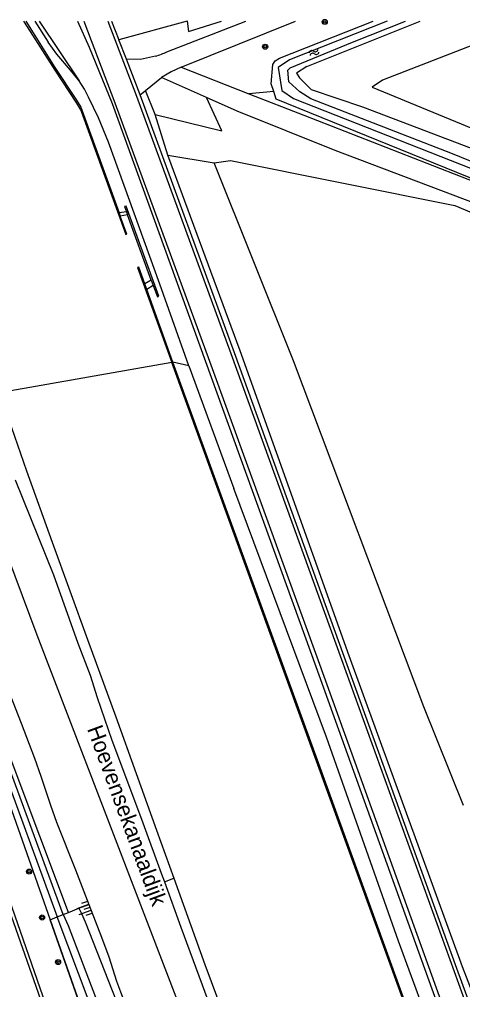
# Model space of a CAD drawing. Extents: x 135990 to 139000, y 393500 to 396000.
# Drawn here: x 136106.6 to 136176.4, y 395847.7 to 396000.3 of the extents above; entities that cross this region are included whole.
import ezdxf

# ---------------------------------------------------------------- set-up
doc = ezdxf.new("R2010")
doc.units = 0
for name, color, linetype in [('gg-afsc-hekwerk', 7, 'Continuous'), ('gg-anno-openbare ruimte label', 7, 'Continuous'), ('gg-knt-BGT kruinlijn', 7, 'Continuous'), ('gg-knt-bovenkant onderkant talud', 7, 'Continuous'), ('gg-knt-onverhard', 7, 'Continuous'), ('gg-knt-verharding', 7, 'Continuous'), ('gg-knt-verharding nz', 7, 'Continuous'), ('gg-kntw-bovenkant insteek waterloop', 7, 'Continuous'), ('gg-kntw-midden sloot', 7, 'Continuous'), ('gg-kntw-waterlijn', 7, 'Continuous'), ('gt-grn-groengrens', 7, 'Continuous'), ('gt-grn-vlakafsluiter', 7, 'Continuous'), ('gt-symb-boom', 7, 'Continuous'), ('gt-symb-talud symbool', 7, 'Continuous'), ('gt-symb-watersymbool', 7, 'Continuous'), ('gx-grn-maaiveld', 7, 'Continuous')]:
    doc.layers.add(name, color=color, linetype=linetype)

# ---------------------------------------------------------------- blocks, each defined once
blk = doc.blocks.new('gt0-BOOM')
at = {"layer": 'gt-symb-boom'}
for radius in [0.4, 0.2]:
    blk.add_circle((0, 0), radius, dxfattribs=at)
blk = doc.blocks.new('gt0-WA')
at = {"layer": 'gt-symb-watersymbool'}
for centre, start, end in [((-0.32, 0.02), 28.0725, 151.9275), ((0.43, 0.42), 208.0725, 331.9275), ((-0.32, -0.43), 28.0725, 151.9275), ((0.43, -0.03), 208.0725, 331.9275)]:
    blk.add_arc(centre, 0.425, start, end, dxfattribs=at)
blk = doc.blocks.new('gt0-TALUD_1')
at = {"layer": 'gt-symb-talud symbool'}
for p, q in [((-1, -1), (-1, 0)), ((-0.5, -2), (-0.5, 0)), ((0, -1), (0, 0)), ((0.5, -2), (0.5, 0)), ((1, -1), (1, 0))]:
    blk.add_line(p, q, dxfattribs=at)

msp = doc.modelspace()

# ---------------------------------------------------------------- linework, layer by layer
at = {"layer": 'gg-afsc-hekwerk'}
for p, q in [((136103.149, 395866.98), (136111.254, 395843.918)), ((136135.1, 395791.647), (136111.438, 395858.672))]:
    msp.add_line(p, q, dxfattribs=at)
for points in [[(136076.591, 395957.119), (136076.633, 395957.112), (136095.22, 395904.613), (136111.438, 395858.672)], [(136076.591, 395957.119), (136076.633, 395957.112), (136095.22, 395904.613), (136111.438, 395858.672)], [(136111.438, 395858.672), (136135.1, 395791.647), (136143.698, 395766.152)]]:
    msp.add_lwpolyline(points, dxfattribs=at)
at = {"layer": 'gg-knt-BGT kruinlijn'}
for p, q in [((136109.036, 396000), (136111.122, 395996.691)), ((136112.493, 395994.843), (136111.122, 395996.691)), ((136114.678, 395992.286), (136112.493, 395994.843)), ((136116.023, 395990.65), (136114.678, 395992.286)), ((136116.853, 395989.334), (136116.023, 395990.65)), ((136117.51, 395988.078), (136116.853, 395989.334)), ((136119.069, 395984.821), (136117.51, 395988.078)), ((136120.666, 395980.986), (136119.069, 395984.821)), ((136128.71, 395958.631), (136120.666, 395980.986)), ((136133.279, 395945.807), (136128.71, 395958.631)), ((136133.279, 395945.807), (136140.36, 395926.532)), ((136105.941, 395927.896), (136111.997, 395912.902)), ((136155.001, 395887.414), (136140.36, 395926.532)), ((136111.997, 395912.902), (136115.811, 395902.193)), ((136115.811, 395902.193), (136117.75, 395897.16)), ((136117.75, 395897.16), (136118.84, 395893.616)), ((136118.84, 395893.616), (136121.177, 395886.922)), ((136121.177, 395886.922), (136122.985, 395882.063)), ((136166.329, 395855.293), (136155.001, 395887.414)), ((136122.985, 395882.063), (136126.058, 395873.896)), ((136126.058, 395873.896), (136128.955, 395866.017)), ((136128.955, 395866.017), (136129.45, 395864.659)), ((136176.285, 395828.31), (136166.329, 395855.293))]:
    msp.add_line(p, q, dxfattribs=at)
msp.add_lwpolyline([(136104.62, 395895.348), (136106.892, 395889.582), (136108.977, 395884.094), (136109.991, 395881.27), (136111.512, 395876.694), (136112.466, 395874.035), (136115.452, 395866.552), (136117.555, 395861.096)], dxfattribs=at)
at = {"layer": 'gg-knt-bovenkant onderkant talud'}
for p, q in [((136109.711, 396000), (136116.023, 395990.65)), ((136130.007, 395978.958), (136137.299, 395977.743))]:
    msp.add_line(p, q, dxfattribs=at)
for points in [[(136201.244, 395796.154), (136195.273, 395801.183), (136192.468, 395809.72), (136176.417, 395851.255), (136158.526, 395900.168), (136141.395, 395948.185), (136130.007, 395978.958)], [(136117.555, 395861.096), (136119.547, 395855.928), (136120.678, 395852.83), (136121.926, 395849.029), (136122.529, 395847.338), (136124.005, 395843.536), (136125.701, 395838.832), (136127.093, 395835.232), (136129.738, 395828.973), (136132.335, 395822.502), (136133.296, 395819.914), (136134.819, 395815.151), (136136.591, 395809.871), (136141.843, 395793), (136143.396, 395788.247), (136144.529, 395785.045), (136145.759, 395781.743), (136149.205, 395772.882)]]:
    msp.add_lwpolyline(points, dxfattribs=at)
at = {"layer": 'gg-knt-onverhard'}
for p, q in [((136132.094, 395992.777), (136142.771, 395988.605)), ((136136.068, 395988.018), (136128.988, 395991.13)), ((136140.928, 395985.882), (136136.068, 395988.018)), ((136142.771, 395988.605), (136151.405, 395985.232))]:
    msp.add_line(p, q, dxfattribs=at)
for points in [[(136260.368, 395939.987), (136258.308, 395935.803), (136256.192, 395938.164), (136254.175, 395939.769), (136251.756, 395941.172), (136238.608, 395946.725), (136200.866, 395962.833), (136156.336, 395979.68), (136140.928, 395985.882)], [(136151.405, 395985.232), (136190.126, 395970.103), (136221.87, 395956.798), (136260.368, 395939.987)]]:
    msp.add_lwpolyline(points, dxfattribs=at)
at = {"layer": 'gg-knt-verharding'}
for p, q in [((136121.108, 396000), (136122.274, 395997.052)), ((136129.859, 395995.215), (136142.248, 396000)), ((136132.094, 395992.777), (136150.119, 396000)), ((136123.474, 395994.021), (136122.274, 395997.052)), ((136126.485, 395989.133), (136128.988, 395991.13)), ((136125.623, 395988.445), (136126.485, 395989.133))]:
    msp.add_line(p, q, dxfattribs=at)
for points in [[(136115.769, 396000), (136117.623, 395995.912), (136121.221, 395987.047), (136153.279, 395898.516), (136170.902, 395849.693), (136186.844, 395805.637)], [(136128.051, 395994.492), (136125.693, 395993.992), (136123.474, 395994.021)], [(136132.094, 395992.777), (136130.499, 395992.033), (136128.988, 395991.13)], [(136194.84, 395798.55), (136194.304, 395799.262), (136191.281, 395807.835), (136175.523, 395851.013), (136140.515, 395947.835), (136125.623, 395988.445)], [(136048.132, 395847.054), (136102.827, 395866.304), (136135.438, 395773.474), (136080.76, 395754.222), (136048.132, 395847.054)]]:
    msp.add_lwpolyline(points, dxfattribs=at)
msp.add_arc((136124.779, 396005.297), 11.289, 286.84862, 296.74327, dxfattribs=at)
at = {"layer": 'gg-knt-verharding nz'}
msp.add_line((136125.623, 395988.445), (136123.474, 395994.021), dxfattribs=at)
for points in [[(136116.757, 396000), (136121.671, 395987.179), (136136.571, 395946.56), (136153.867, 395898.856), (136171.516, 395849.993), (136187.438, 395805.778), (136189.89, 395798.04), (136191.937, 395790.186), (136193.392, 395784.681), (136195.054, 395779.234), (136195.542, 395777.827)], [(136120.537, 396000), (136125.042, 395988.226), (136139.915, 395947.719), (136157.35, 395899.595), (136190.76, 395807.111), (136192.059, 395803.156), (136193.814, 395797.163), (136196.045, 395788.338), (136197.62, 395782.842), (136198.877, 395779.004)]]:
    msp.add_lwpolyline(points, dxfattribs=at)
at = {"layer": 'gg-kntw-bovenkant insteek waterloop'}
for p, q in [((136133.054, 395999.996), (136133.065, 396000)), ((136151.86, 395992.871), (136169.706, 396000))]:
    msp.add_line(p, q, dxfattribs=at)
for points in [[(136133.054, 395999.996), (136133.25, 395998.381), (136138.46, 396000)], [(136146.534, 395993.193), (136146.884, 395993.798), (136147.584, 395994.202), (136162.341, 396000)], [(136146.665, 395988.937), (136146.269, 395990.152), (136146.534, 395993.193)], [(136151.86, 395992.871), (136150.244, 395991.832), (136150.736, 395991.101), (136152.541, 395989.289), (136160.654, 395986.547), (136187.413, 395976.377), (136267.176, 395941.857), (136279.571, 395934.316), (136290.57, 395925.713), (136327.125, 395886.537)], [(136260.701, 395940.796), (136211.178, 395961.745), (136147.051, 395987.75), (136146.665, 395988.937)], [(136114.344, 395859.824), (136100.745, 395895.836), (136087.665, 395933.499), (136076.623, 395963.97), (136074.337, 395963.35)]]:
    msp.add_lwpolyline(points, dxfattribs=at)
at = {"layer": 'gg-kntw-midden sloot'}
for points in [[(136137.299, 395977.743), (136139.863, 395978.077), (136175.196, 395970.996), (136225.687, 395949.807)], [(136176.537, 395876.661), (136170.293, 395892.151), (136149.783, 395946.573), (136137.299, 395977.743)]]:
    msp.add_lwpolyline(points, dxfattribs=at)
at = {"layer": 'gg-kntw-waterlijn'}
for points in [[(136164.548, 396000), (136149.157, 395993.938), (136147.368, 395992.701), (136147.921, 395989.122), (136149.771, 395987.857), (136187.797, 395972.933), (136249.43, 395946.591), (136268.682, 395938.154), (136274.582, 395934.054), (136288.114, 395924.649)], [(136279.098, 395932.901), (136270.859, 395938.459), (136260.015, 395943.136), (136230.027, 395956.07), (136206.184, 395966.352), (136174.835, 395979.164), (136152.487, 395987.78), (136150.787, 395988.875), (136149.064, 395990.487), (136148.872, 395992.283), (136149.276, 395992.676), (136159.047, 395996.687), (136167.434, 396000)], [(136113.492, 395859.486), (136096.948, 395904.455), (136087.39, 395933.074), (136076.227, 395962.85), (136075.297, 395962.501), (136103.1, 395884.834), (136112.551, 395859.113)]]:
    msp.add_lwpolyline(points, dxfattribs=at)
at = {"layer": 'gt-grn-groengrens'}
for p, q in [((136133.054, 395999.996), (136122.274, 395997.052)), ((136127.975, 395985.357), (136126.485, 395989.133)), ((136146.665, 395988.937), (136142.771, 395988.605)), ((136130.007, 395978.958), (136127.975, 395985.357))]:
    msp.add_line(p, q, dxfattribs=at)
for points in [[(136187.706, 396000), (136163.811, 395990.712), (136162.186, 395989.628), (136200.373, 395973.92), (136241.539, 395956.317), (136268.351, 395944.942), (136282.705, 395934.921), (136298.142, 395923.546), (136313.308, 395906.755), (136329.847, 395889.355)], [(136127.975, 395985.357), (136138.483, 395982.789), (136136.068, 395988.018)]]:
    msp.add_lwpolyline(points, dxfattribs=at)
at = {"layer": 'gt-grn-vlakafsluiter'}
for p, q in [((136112.551, 395859.113), (136113.492, 395859.486)), ((136113.492, 395859.486), (136114.344, 395859.824)), ((136111.438, 395858.672), (136112.551, 395859.113))]:
    msp.add_line(p, q, dxfattribs=at)
at = {"layer": 'gx-grn-maaiveld'}
for p, q in [((136116.516, 395985.914), (136116.346, 395985.853)), ((136116.516, 395985.914), (136122.323, 395969.858)), ((136123.476, 395970.045), (136122.323, 395969.858)), ((136122.323, 395969.858), (136122.509, 395969.344)), ((136123.653, 395969.558), (136122.509, 395969.344)), ((136123.476, 395970.045), (136123.653, 395969.558)), ((136127.387, 395959.285), (136123.653, 395969.558)), ((136127.387, 395959.285), (136126.35, 395958.705)), ((136126.668, 395957.823), (136126.35, 395958.705)), ((136127.692, 395958.445), (136126.668, 395957.823)), ((136127.387, 395959.285), (136127.692, 395958.445)), ((136130.791, 395946.399), (136126.668, 395957.823)), ((136130.626, 395946.34), (136103.428, 395941.529)), ((136130.791, 395946.399), (136130.626, 395946.34)), ((136133.279, 395945.807), (136130.791, 395946.399)), ((136129.45, 395864.659), (136130.928, 395865.231)), ((136115.98, 395860.472), (136117.555, 395861.096)), ((136114.344, 395859.824), (136115.98, 395860.472))]:
    msp.add_line(p, q, dxfattribs=at)
for points in [[(136107.287, 396000), (136108.313, 395998.374), (136112.182, 395992.303), (136115.588, 395987.116), (136116.23, 395986.053), (136116.346, 395985.853)], [(136107.647, 396000), (136108.761, 395998.198), (136112.222, 395992.742), (136115.606, 395987.567), (136116.3, 395986.513), (136116.516, 395985.914)], [(136116.346, 395985.853), (136123.366, 395966.458), (136123.531, 395966.518), (136122.509, 395969.344)], [(136127.692, 395958.445), (136128.338, 395956.667), (136128.596, 395956.761), (136123.443, 395970.94), (136123.185, 395970.846), (136123.476, 395970.045)], [(136164.711, 395751.666), (136162.661, 395758.829), (136160.097, 395769.164), (136157.652, 395776.684), (136154.592, 395786.426), (136136.857, 395832.005), (136109.394, 395903.412), (136089.873, 395955.63), (136086.811, 395965.15), (136083.551, 395969.67)], [(136126.35, 395958.705), (136125.4, 395961.338), (136125.235, 395961.279), (136130.626, 395946.34)], [(136191.818, 395777.417), (136182.208, 395804.311), (136130.626, 395946.34)], [(136191.912, 395777.451), (136179.933, 395811.067), (136153.962, 395882.618), (136130.791, 395946.399)], [(136103.428, 395941.529), (136107.741, 395929.307), (136111.773, 395918.048), (136117.329, 395902.744), (136121.777, 395890.587), (136128.222, 395872.773), (136130.928, 395865.231)], [(136129.45, 395864.659), (136132.045, 395857.531), (136136.268, 395846.024)], [(136130.928, 395865.231), (136135.798, 395851.662), (136139.627, 395841.335)], [(136113.492, 395859.486), (136114.281, 395857.755), (136126.934, 395824.645), (136141.281, 395786.093), (136147.123, 395769.755), (136145.525, 395769.157), (136141.832, 395779.161), (136128.016, 395818.182), (136112.551, 395859.113)], [(136115.98, 395860.472), (136116.408, 395859.644), (136116.981, 395858.345), (136123.076, 395842.906), (136128.333, 395826.927), (136133.307, 395814.071), (136138.663, 395801.236), (136142.13, 395791.065), (136145.356, 395781.821), (136147.46, 395774.422), (136147.921, 395772.069), (136148.229, 395770.353), (136148.177, 395769.146), (136147.829, 395768.14), (136147.272, 395767.66), (136146.029, 395767.512), (136144.847, 395767.987), (136143.953, 395769.002), (136143.134, 395770.943), (136141.896, 395773.966), (136135.1, 395791.647)]]:
    msp.add_lwpolyline(points, dxfattribs=at)

# ---------------------------------------------------------------- block references
at = {"layer": 'gt-symb-boom'}
for p in [(136154.702, 395999.891), (136145.313, 395996.001), (136108.139, 395866.248), (136110.186, 395859.03), (136112.705, 395852.016)]:
    msp.add_blockref('gt0-BOOM', p, dxfattribs=at)
at = {"layer": 'gt-symb-talud symbool', "xscale": 1.0000284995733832, "yscale": 1.0000284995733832, "rotation": -69.8798342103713}
msp.add_blockref('gt0-TALUD_1', (136117.739, 395860.667), dxfattribs=at)
at = {"layer": 'gt-symb-watersymbool', "rotation": 21.663039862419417}
msp.add_blockref('gt0-WA', (136152.953, 395995.075), dxfattribs=at)

# ---------------------------------------------------------------- texts
at = {"layer": 'gg-anno-openbare ruimte label'}
msp.add_text('Hoevensekanaaldijk', height=2.5, rotation=290.2, dxfattribs=at).set_placement((136117.242, 395888.71))

doc.saveas('drawing.dxf')
